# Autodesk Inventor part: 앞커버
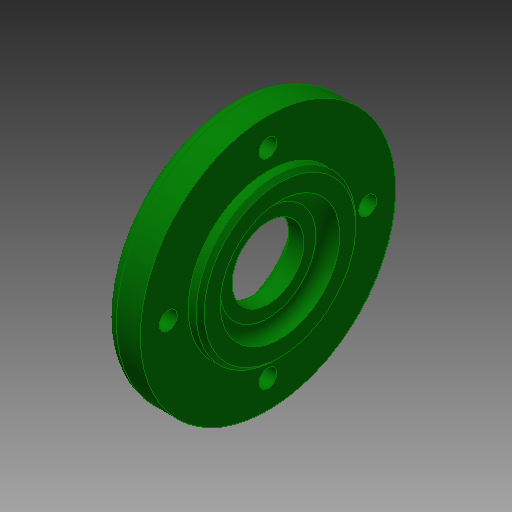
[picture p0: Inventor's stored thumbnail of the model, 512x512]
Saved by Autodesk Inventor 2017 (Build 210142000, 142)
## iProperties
Created: 2020-07
Part Number: 앞커버
Material: 알루미늄 6061
Document SubType Name: Modeling
Designer: mduedu
Density: 2.71 g/cm^3
Appearance: 진녹색
Mass: 66.4286 g
Surface Area: 91.7138 cm^2
Volume: 24.5124 cm^3
Author: mduedu
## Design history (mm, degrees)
sketch "스케치1"
  geometry: L1 (0, 0)-(9, 0); L2 (9, 0)-(9, 32); L3 (9, 32)-(0, 32); L4 (0, 32)-(0, 0); L5 (9, 0)-(12, 0); L6 (12, 0)-(12, 20); L7 (12, 20)-(9, 20); L8 (9, 20)-(9, 0)
  constraints: 16 end point, 4 parallel, 2 horizontal, 2 perpendicular
  dimensions: "d0" = 64 diameter of L3 L1; "d2" = 40 diameter of L7 L5; "d3" = 12 distance between parallel lines of L6 L4; "d4" = 3 distance between parallel lines of L2 L6
revolve "회전1" sketch "스케치1" stored, may be unused: angle "d5" = 90 deg
sketch "스케치2"
  geometry: L1 (0, -32)-(0, 32) reference; L2 (0, 32)-(9, 32) reference; L3 (9, 32)-(9, 20) reference; L4 (9, 20)-(12, 20) reference; L5 (12, 20)-(12, -20) reference; L6 (12, -20)-(9, -20) reference; L7 (9, -20)-(9, -32) reference; L8 (9, -32)-(0, -32) reference; L9 (0, 0)-(5.2, 0); L10 (5.2, 0)-(5.2, 15); L11 (5.2, 15)-(0, 15); L12 (0, 15)-(0, 0); L13 (5.2, 0)-(9, 0); L14 (9, 0)-(9, 9); L15 (9, 9)-(5.2, 9); L16 (5.2, 9)-(5.2, 0); L17 (9, 0)-(12, 0); L18 (12, 0)-(12, 15); L19 (12, 15)-(9, 15); L20 (9, 15)-(9, 0)
  constraints: 24 end point, 6 parallel, 3 horizontal, 3 perpendicular, 1 point on line
  dimensions: "d6" = 30 diameter of L11 L9; "d8" = 18 diameter of L15 L13; "d9" = 30 diameter of L19 L17; "d10" = 3 distance of L18.end L19.end; "d11" = 5.2 distance of L10.end L11.end
revolve "회전2" sketch "스케치2" stored, may be unused: angle "d12" = 90 deg
fillet "모깎기1" dims "d13" = 3
fillet "모깎기2" dims "d14" = 3
chamfer "모따기1" distance "d15" = 1; stored, may be unused: second distance "d16" = 2, angle "d17" = 45 deg
sketch "스케치3" dims "d18" = 50
  geometry: 3 further points
  constraints: 2 vertical alignment, 1 coincident, 2 other
hole "구멍1" sketch "스케치3" at (0, 25) diameter "d19" = 4.5; stored, may be unused: countersink angle "d23" = 90 deg, drill point angle "d25" = 118 deg; dims "d20" = 6, "d21" = 8, "d22" = 4.4, "d24" = 8
fillet "모깎기3" dims "d29" = 0.5
chamfer "모따기2" distance "d30" = 0.5; stored, may be unused: second distance "d31" = 2, angle "d32" = 30 deg
node "솔리드1"
pattern_circular "원형 패턴1" dims angle "d27" = 360 deg
node "절단 모서리 투영1"
